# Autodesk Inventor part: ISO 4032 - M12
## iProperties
Created: 2001-12
Part Number: ISO 4032 - M12
Catalog Web Link: file:///F:/Cad/Autodesk/Inventor 5/Content/Iso/index.htm?doNavigateId=81B6DECA-D49F-45EF-94B6-61B88B49772D|F0100A5F59104064B8BFC37D67EBD9B|true
Description: Hex Nut
Document SubType Name: Standard Catalog Part
Standard: ISO 4032 - M12
Designer: Tobben
Control State: 0
Master: False
Checked Out: False
Shininess: 64.0
Length Units: 11269
Angle Units: 11279
Time Units: 11290
Mass Units: 11283
Length Display Precision: 3
Angle Display Precision: 2
Compacted: True
CLASSIFICATION: 31161727 un/spsc
MANUFACTURER: ISO Standard System
Density: 0.0
Volumn: 0.0
Area: 0.0
PropertySet Name: Model Information
Author: Tobben
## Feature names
1. Base1
